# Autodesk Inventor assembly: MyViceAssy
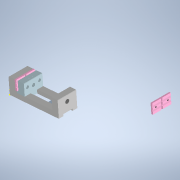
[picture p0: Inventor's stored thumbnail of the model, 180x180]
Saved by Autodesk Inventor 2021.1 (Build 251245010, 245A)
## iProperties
Created: 2020-12
Part Number: MyViceAssy
Document SubType Name: Assembly
Designer: BALA
Author: BALA
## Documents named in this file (8)
- H:\Inventor\BALA Project\MyViceAssy.iam
- H:\Inventor\BALA Project\20201218Base.ipt
- H:\Inventor\BALA Project\FixEnd.ipt
- C:\Users\balat\Documents\Inventor\Content Center Files\R2021\en-US\DIN 6912\DIN 6912 - M5 x 25.ipt
- H:\Inventor\BALA Project\ScrewEnd.ipt
- H:\Inventor\BALA Project\Jaws.ipt
- H:\Inventor\BALA Project\SupportBracket.ipt
- H:\Inventor\BALA Project\Move End.ipt
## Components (11 placed, 7 different names)
1. 20201218Base:1 — Flush:1, Flush:2, Mate:1, Insert:1, Insert:2, Flush:3, Flush:4, Mate:4, Insert:3, Insert:4, Mate:7, Mate:8, Flush:6, Mate:9, Flush:7
2. FixEnd:1 — Flush:1, Flush:2, Mate:1, Mate:2, Mate:3, Mate:5, Flush:5, Mate:6
3. DIN 6912 M5 x 25:1 — Insert:1
4. DIN 6912 M5 x 25:2 — Insert:2
5. ScrewEnd:1 — Flush:3, Flush:4, Mate:4, Mate:10
6. DIN 6912 M5 x 25:3 — Insert:3
7. DIN 6912 M5 x 25:4 — Insert:4
8. Jaws:1 — Mate:5, Flush:5, Mate:6
9. Jaws:2
10. SupportBracket:1 — Mate:7, Mate:8, Flush:6
11. Move End:1 — Mate:9, Flush:7, Mate:10
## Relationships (21: Mate 10, Flush 7, Insert 4)
- Flush:1: 20201218Base:1 ↔ FixEnd:1
- Flush:2: 20201218Base:1 ↔ FixEnd:1
- Mate:1: 20201218Base:1 ↔ FixEnd:1
- Mate:2: FixEnd:1
- Mate:3: FixEnd:1
- Insert:1: 20201218Base:1 ↔ DIN 6912 M5 x 25:1
- Insert:2: 20201218Base:1 ↔ DIN 6912 M5 x 25:2
- Flush:3: 20201218Base:1 ↔ ScrewEnd:1
- Flush:4: 20201218Base:1 ↔ ScrewEnd:1
- Mate:4: 20201218Base:1 ↔ ScrewEnd:1
- Insert:3: 20201218Base:1 ↔ DIN 6912 M5 x 25:3
- Insert:4: 20201218Base:1 ↔ DIN 6912 M5 x 25:4
- Mate:5: FixEnd:1 ↔ Jaws:1
- Flush:5: FixEnd:1 ↔ Jaws:1
- Mate:6: FixEnd:1 ↔ Jaws:1
- Mate:7: 20201218Base:1 ↔ SupportBracket:1
- Mate:8: 20201218Base:1 ↔ SupportBracket:1
- Flush:6: 20201218Base:1 ↔ SupportBracket:1
- Mate:9: 20201218Base:1 ↔ Move End:1
- Flush:7: 20201218Base:1 ↔ Move End:1
- Mate:10: ScrewEnd:1 ↔ Move End:1
